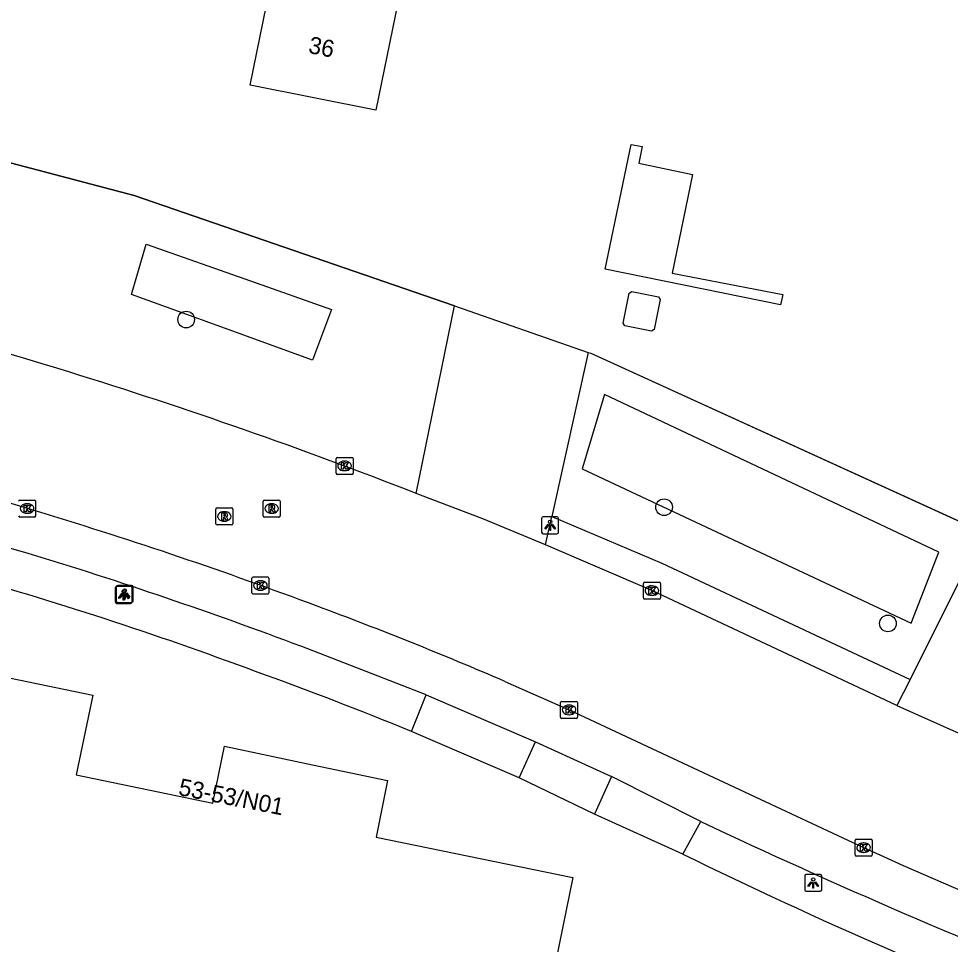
# Model space of a CAD drawing. Extents: x 157692 to 159670, y 381454 to 383289.
# Drawn here: x 158119.2 to 158173.9, y 381831.4 to 381885.7 of the extents above; entities that cross this region are included whole.
import ezdxf

# ---------------------------------------------------------------- set-up
doc = ezdxf.new("R2010")
doc.units = 0
for name, color, linetype in [('IMGEO_Berm_groen', 7, 'Continuous'), ('IMGEO_Boom', 7, 'Continuous'), ('IMGEO_Groenvoorziening', 7, 'Continuous'), ('IMGEO_Hek', 7, 'Continuous'), ('IMGEO_Kolk', 7, 'Continuous'), ('IMGEO_Lichtpunt', 7, 'Continuous'), ('IMGEO_Pand', 7, 'Continuous'), ('IMGEO_Pand_nummerreeks', 7, 'Continuous'), ('IMGEO_Rijbaan_lokaal_gesloten', 7, 'Continuous'), ('IMGEO_Rijbaan_lokaal_open', 7, 'Continuous'), ('IMGEO_Rioolput', 7, 'Continuous'), ('IMGEO_Voetpad_open', 7, 'Continuous'), ('IMGEO_Waterloop', 7, 'Continuous')]:
    doc.layers.add(name, color=color, linetype=linetype)

msp = doc.modelspace()

# ---------------------------------------------------------------- linework, layer by layer
at = {"layer": 'IMGEO_Berm_groen'}
msp.add_lwpolyline([(158144.779, 381868.849), (158125.96, 381875.333), (158105.527, 381880.719), (158105.432, 381880.499)], dxfattribs=at)
at = {"layer": 'IMGEO_Boom'}
for centre in [(158129.018, 381868.054), (158157.094, 381857.037), (158170.245, 381850.21)]:
    msp.add_circle(centre, 0.489, dxfattribs=at)
at = {"layer": 'IMGEO_Groenvoorziening'}
msp.add_lwpolyline([(158152.635, 381866.121), (158152.79, 381866.076), (158175.894, 381855.545)], dxfattribs=at)
at = {"layer": 'IMGEO_Hek'}
for points in [[(158105.432, 381880.499), (158105.527, 381880.719), (158125.96, 381875.333), (158144.779, 381868.849)], [(158144.779, 381868.849), (158152.635, 381866.121)], [(158152.635, 381866.121), (158152.79, 381866.076), (158181.715, 381852.892), (158201.637, 381844.863)]]:
    msp.add_lwpolyline(points, dxfattribs=at)
at = {"layer": 'IMGEO_Kolk'}
for p, q in [((158137.896, 381859.961), (158138.748, 381859.961)), ((158137.821, 381859.035), (158137.821, 381859.887)), ((158138.309, 381859.741), (158138.334, 381859.741)), ((158138.822, 381859.887), (158138.822, 381859.035)), ((158138.748, 381858.961), (158137.896, 381858.961)), ((158138.332, 381859.181), (158138.307, 381859.181)), ((158119.251, 381857.458), (158120.103, 381857.458)), ((158119.664, 381857.238), (158119.689, 381857.238)), ((158120.177, 381857.384), (158120.177, 381856.532)), ((158119.687, 381856.678), (158119.662, 381856.678)), ((158120.103, 381856.458), (158119.251, 381856.458)), ((158132.883, 381852.014), (158132.883, 381852.866)), ((158132.958, 381852.94), (158133.81, 381852.94)), ((158133.884, 381852.866), (158133.884, 381852.014)), ((158133.371, 381852.72), (158133.396, 381852.72)), ((158155.877, 381851.714), (158155.877, 381852.566)), ((158155.952, 381852.64), (158156.804, 381852.64)), ((158156.365, 381852.42), (158156.39, 381852.42)), ((158156.878, 381852.566), (158156.878, 381851.714)), ((158133.81, 381851.94), (158132.958, 381851.94)), ((158133.394, 381852.16), (158133.369, 381852.16)), ((158156.388, 381851.86), (158156.363, 381851.86)), ((158156.804, 381851.64), (158155.952, 381851.64)), ((158151.012, 381844.709), (158151.012, 381845.561)), ((158151.087, 381845.635), (158151.939, 381845.635)), ((158151.5, 381845.415), (158151.525, 381845.415)), ((158152.013, 381845.561), (158152.013, 381844.709)), ((158151.939, 381844.635), (158151.087, 381844.635)), ((158151.523, 381844.855), (158151.498, 381844.855)), ((158168.39, 381837.55), (158169.242, 381837.55)), ((158168.315, 381836.624), (158168.315, 381837.476)), ((158168.803, 381837.33), (158168.828, 381837.33)), ((158169.316, 381837.476), (158169.316, 381836.624)), ((158169.242, 381836.55), (158168.39, 381836.55)), ((158168.826, 381836.77), (158168.801, 381836.77))]:
    msp.add_line(p, q, dxfattribs=at)
for points in [[(158137.896, 381859.961), (158138.748, 381859.961)], [(158137.821, 381859.035), (158137.821, 381859.887)], [(158138.142, 381859.661), (158138.265, 381859.661), (158138.265, 381859.51), (158138.395, 381859.661), (158138.559, 381859.661), (158138.413, 381859.51), (158138.566, 381859.261), (158138.414, 381859.261), (158138.329, 381859.425), (158138.265, 381859.358), (158138.265, 381859.261), (158138.142, 381859.261), (158138.142, 381859.661)], [(158138.822, 381859.887), (158138.822, 381859.035)], [(158138.748, 381858.961), (158137.896, 381858.961)], [(158119.251, 381857.458), (158120.103, 381857.458)], [(158120.177, 381857.384), (158120.177, 381856.532)], [(158119.497, 381857.158), (158119.62, 381857.158), (158119.62, 381857.007), (158119.75, 381857.158), (158119.914, 381857.158), (158119.768, 381857.007), (158119.921, 381856.758), (158119.769, 381856.758), (158119.684, 381856.922), (158119.62, 381856.855), (158119.62, 381856.758), (158119.497, 381856.758), (158119.497, 381857.158)], [(158120.103, 381856.458), (158119.251, 381856.458)], [(158132.883, 381852.014), (158132.883, 381852.866)], [(158132.958, 381852.94), (158133.81, 381852.94)], [(158133.884, 381852.866), (158133.884, 381852.014)], [(158133.204, 381852.64), (158133.327, 381852.64), (158133.327, 381852.489), (158133.457, 381852.64), (158133.621, 381852.64), (158133.475, 381852.489), (158133.628, 381852.24), (158133.476, 381852.24), (158133.391, 381852.404), (158133.327, 381852.337), (158133.327, 381852.24), (158133.204, 381852.24), (158133.204, 381852.64)], [(158155.877, 381851.714), (158155.877, 381852.566)], [(158155.952, 381852.64), (158156.804, 381852.64)], [(158156.198, 381852.34), (158156.321, 381852.34), (158156.321, 381852.189), (158156.451, 381852.34), (158156.615, 381852.34), (158156.469, 381852.189), (158156.622, 381851.94), (158156.47, 381851.94), (158156.385, 381852.104), (158156.321, 381852.037), (158156.321, 381851.94), (158156.198, 381851.94), (158156.198, 381852.34)], [(158156.878, 381852.566), (158156.878, 381851.714)], [(158133.81, 381851.94), (158132.958, 381851.94)], [(158156.804, 381851.64), (158155.952, 381851.64)], [(158151.012, 381844.709), (158151.012, 381845.561)], [(158151.087, 381845.635), (158151.939, 381845.635)], [(158151.333, 381845.335), (158151.456, 381845.335), (158151.456, 381845.184), (158151.586, 381845.335), (158151.75, 381845.335), (158151.604, 381845.184), (158151.757, 381844.935), (158151.605, 381844.935), (158151.52, 381845.099), (158151.456, 381845.032), (158151.456, 381844.935), (158151.333, 381844.935), (158151.333, 381845.335)], [(158152.013, 381845.561), (158152.013, 381844.709)], [(158151.939, 381844.635), (158151.087, 381844.635)], [(158168.39, 381837.55), (158169.242, 381837.55)], [(158168.315, 381836.624), (158168.315, 381837.476)], [(158168.636, 381837.25), (158168.759, 381837.25), (158168.759, 381837.099), (158168.889, 381837.25), (158169.053, 381837.25), (158168.907, 381837.099), (158169.06, 381836.85), (158168.908, 381836.85), (158168.823, 381837.014), (158168.759, 381836.947), (158168.759, 381836.85), (158168.636, 381836.85), (158168.636, 381837.25)], [(158169.316, 381837.476), (158169.316, 381836.624)], [(158169.242, 381836.55), (158168.39, 381836.55)]]:
    msp.add_lwpolyline(points, dxfattribs=at)
for centre, start, end in [((158137.898, 381859.885), 91.552, 178.448), ((158137.898, 381859.885), 91.552, 178.448), ((158138.746, 381859.885), 1.552, 88.448), ((158138.746, 381859.885), 1.552, 88.448), ((158137.898, 381859.037), 181.552, 268.448), ((158137.898, 381859.037), 181.552, 268.448), ((158138.746, 381859.037), 271.552, 358.448), ((158138.746, 381859.037), 271.552, 358.448), ((158119.253, 381857.382), 91.552, 178.448), ((158119.253, 381857.382), 91.552, 178.448), ((158120.101, 381857.382), 1.552, 88.448), ((158120.101, 381857.382), 1.552, 88.448), ((158119.253, 381856.534), 181.552, 268.448), ((158119.253, 381856.534), 181.552, 268.448), ((158120.101, 381856.534), 271.552, 358.448), ((158120.101, 381856.534), 271.552, 358.448), ((158132.96, 381852.864), 91.552, 178.448), ((158132.96, 381852.864), 91.552, 178.448), ((158133.808, 381852.864), 1.552, 88.448), ((158133.808, 381852.864), 1.552, 88.448), ((158155.954, 381852.564), 91.552, 178.448), ((158155.954, 381852.564), 91.552, 178.448), ((158156.802, 381852.564), 1.552, 88.448), ((158156.802, 381852.564), 1.552, 88.448), ((158132.96, 381852.016), 181.552, 268.448), ((158132.96, 381852.016), 181.552, 268.448), ((158133.808, 381852.016), 271.552, 358.448), ((158133.808, 381852.016), 271.552, 358.448), ((158155.954, 381851.716), 181.552, 268.448), ((158155.954, 381851.716), 181.552, 268.448), ((158156.802, 381851.716), 271.552, 358.448), ((158156.802, 381851.716), 271.552, 358.448), ((158151.089, 381845.559), 91.552, 178.448), ((158151.089, 381845.559), 91.552, 178.448), ((158151.937, 381845.559), 1.552, 88.448), ((158151.937, 381845.559), 1.552, 88.448), ((158151.089, 381844.711), 181.552, 268.448), ((158151.089, 381844.711), 181.552, 268.448), ((158151.937, 381844.711), 271.552, 358.448), ((158151.937, 381844.711), 271.552, 358.448), ((158168.392, 381837.474), 91.552, 178.448), ((158168.392, 381837.474), 91.552, 178.448), ((158169.24, 381837.474), 1.552, 88.448), ((158169.24, 381837.474), 1.552, 88.448), ((158168.392, 381836.626), 181.552, 268.448), ((158168.392, 381836.626), 181.552, 268.448), ((158169.24, 381836.626), 271.552, 358.448), ((158169.24, 381836.626), 271.552, 358.448)]:
    msp.add_arc(centre, 0.0765, start, end, dxfattribs=at)
for centre, major_axis, ratio, start_param, end_param in [((158138.308, 381859.461), (-0.387, 0.002), 0.722429, 4.712389, 7.853982), ((158138.333, 381859.461), (-0.39, 0.002), 0.717154, 1.570796, 4.712389), ((158119.663, 381856.958), (-0.387, 0.002), 0.722429, 4.712389, 7.853982), ((158119.688, 381856.958), (-0.39, 0.002), 0.717154, 1.570796, 4.712389), ((158133.37, 381852.44), (-0.387, 0.002), 0.722429, 4.712389, 7.853982), ((158133.395, 381852.44), (-0.39, 0.002), 0.717154, 1.570796, 4.712389), ((158156.364, 381852.14), (-0.387, 0.002), 0.722429, 4.712389, 7.853982), ((158156.389, 381852.14), (-0.39, 0.002), 0.717154, 1.570796, 4.712389), ((158151.499, 381845.135), (-0.387, 0.002), 0.722429, 4.712389, 7.853982), ((158151.524, 381845.135), (-0.39, 0.002), 0.717154, 1.570796, 4.712389), ((158168.802, 381837.05), (-0.387, 0.002), 0.722429, 4.712389, 7.853982), ((158168.827, 381837.05), (-0.39, 0.002), 0.717154, 1.570796, 4.712389)]:
    msp.add_ellipse(centre, major_axis=major_axis, ratio=ratio, start_param=start_param, end_param=end_param, dxfattribs=at)
at = {"layer": 'IMGEO_Lichtpunt'}
for p, q in [((158149.902, 381856.378), (158149.902, 381855.571)), ((158149.902, 381856.378), (158149.902, 381855.571)), ((158150.804, 381856.473), (158149.996, 381856.473)), ((158150.804, 381856.473), (158149.996, 381856.473)), ((158150.898, 381855.571), (158150.898, 381856.378)), ((158150.898, 381855.571), (158150.898, 381856.378)), ((158149.996, 381855.477), (158150.804, 381855.477)), ((158149.996, 381855.477), (158150.804, 381855.477)), ((158124.851, 381852.293), (158124.851, 381851.486)), ((158124.851, 381852.293), (158124.851, 381851.486)), ((158124.907, 381852.349), (158124.907, 381851.542)), ((158124.907, 381852.349), (158124.907, 381851.542)), ((158125.753, 381852.388), (158124.945, 381852.388)), ((158125.753, 381852.388), (158124.945, 381852.388)), ((158125.809, 381852.444), (158125.001, 381852.444)), ((158125.809, 381852.444), (158125.001, 381852.444)), ((158125.847, 381851.486), (158125.847, 381852.293)), ((158125.847, 381851.486), (158125.847, 381852.293)), ((158125.903, 381851.542), (158125.903, 381852.349)), ((158125.903, 381851.542), (158125.903, 381852.349)), ((158124.945, 381851.392), (158125.753, 381851.392)), ((158124.945, 381851.392), (158125.753, 381851.392)), ((158125.001, 381851.448), (158125.809, 381851.448)), ((158125.001, 381851.448), (158125.809, 381851.448)), ((158165.357, 381835.385), (158165.357, 381834.578)), ((158165.357, 381835.385), (158165.357, 381834.578)), ((158166.259, 381835.48), (158165.451, 381835.48)), ((158166.259, 381835.48), (158165.451, 381835.48)), ((158166.353, 381834.578), (158166.353, 381835.385)), ((158166.353, 381834.578), (158166.353, 381835.385)), ((158165.451, 381834.484), (158166.259, 381834.484)), ((158165.451, 381834.484), (158166.259, 381834.484))]:
    msp.add_line(p, q, dxfattribs=at)
for points in [[(158150.276, 381856.042), (158150.315, 381856.014), (158150.127, 381855.752), (158150.089, 381855.779), (158150.276, 381856.042)], [(158150.378, 381855.994), (158150.425, 381855.994), (158150.425, 381855.672), (158150.378, 381855.672), (158150.378, 381855.994)], [(158150.488, 381856.014), (158150.526, 381856.041), (158150.713, 381855.779), (158150.674, 381855.751), (158150.488, 381856.014)], [(158125.225, 381851.957), (158125.264, 381851.929), (158125.076, 381851.667), (158125.038, 381851.694), (158125.225, 381851.957)], [(158125.281, 381852.013), (158125.32, 381851.985), (158125.132, 381851.723), (158125.094, 381851.75), (158125.281, 381852.013)], [(158125.327, 381851.909), (158125.374, 381851.909), (158125.374, 381851.587), (158125.327, 381851.587), (158125.327, 381851.909)], [(158125.383, 381851.965), (158125.43, 381851.965), (158125.43, 381851.643), (158125.383, 381851.643), (158125.383, 381851.965)], [(158125.437, 381851.929), (158125.475, 381851.956), (158125.662, 381851.694), (158125.623, 381851.666), (158125.437, 381851.929)], [(158125.493, 381851.985), (158125.531, 381852.012), (158125.718, 381851.75), (158125.679, 381851.722), (158125.493, 381851.985)], [(158165.731, 381835.049), (158165.77, 381835.021), (158165.582, 381834.759), (158165.544, 381834.786), (158165.731, 381835.049)], [(158165.833, 381835.001), (158165.88, 381835.001), (158165.88, 381834.679), (158165.833, 381834.679), (158165.833, 381835.001)], [(158165.943, 381835.021), (158165.981, 381835.048), (158166.168, 381834.786), (158166.129, 381834.758), (158165.943, 381835.021)]]:
    msp.add_lwpolyline(points, dxfattribs=at)
for centre in [(158150.401, 381856.176), (158125.35, 381852.091), (158125.406, 381852.147), (158165.856, 381835.183)]:
    msp.add_circle(centre, 0.0994, dxfattribs=at)
for centre, start, end in [((158149.996, 381856.378), 90, 180), ((158149.996, 381856.378), 90, 180), ((158150.804, 381856.378), 0, 90), ((158150.804, 381856.378), 0, 90), ((158149.996, 381855.571), 180, 270), ((158149.996, 381855.571), 180, 270), ((158150.804, 381855.571), 270, 0), ((158150.804, 381855.571), 270, 360), ((158124.945, 381852.293), 90, 180), ((158124.945, 381852.293), 90, 180), ((158125.001, 381852.349), 90, 180), ((158125.001, 381852.349), 90, 180), ((158125.753, 381852.293), 0, 90), ((158125.753, 381852.293), 0, 90), ((158125.809, 381852.349), 0, 90), ((158125.809, 381852.349), 0, 90), ((158124.945, 381851.486), 180, 270), ((158124.945, 381851.486), 180, 270), ((158125.001, 381851.542), 180, 270), ((158125.001, 381851.542), 180, 270), ((158125.753, 381851.486), 270, 0), ((158125.753, 381851.486), 270, 360), ((158125.809, 381851.542), 270, 0), ((158125.809, 381851.542), 270, 360), ((158165.451, 381835.385), 90, 180), ((158165.451, 381835.385), 90, 180), ((158166.259, 381835.385), 0, 90), ((158166.259, 381835.385), 0, 90), ((158165.451, 381834.578), 180, 270), ((158165.451, 381834.578), 180, 270), ((158166.259, 381834.578), 270, 0), ((158166.259, 381834.578), 270, 360)]:
    msp.add_arc(centre, 0.0946, start, end, dxfattribs=at)
at = {"layer": 'IMGEO_Pand'}
for points in [[(158150.089, 381901.741), (158149.404, 381898.409), (158148.396, 381893.511), (158143.672, 381890.398), (158142.279, 381890.684), (158140.153, 381880.347), (158132.778, 381881.818), (158134.901, 381892.186), (158133.538, 381892.467), (158130.421, 381897.187), (158131.806, 381903.957)], [(158164.062, 381869.533), (158163.943, 381868.909), (158153.641, 381871.004), (158155.165, 381878.336), (158155.808, 381878.218), (158155.605, 381877.228), (158158.771, 381876.571), (158157.567, 381870.772), (158164.062, 381869.533)], [(158156.503, 381867.463), (158156.361, 381867.369), (158154.784, 381867.69), (158154.69, 381867.832), (158155.051, 381869.606), (158155.193, 381869.7), (158156.77, 381869.379), (158156.864, 381869.237), (158156.503, 381867.463)], [(158102.734, 381825.813), (158104.044, 381832.191), (158104.164, 381832.773), (158101.359, 381833.35), (158101.783, 381835.271), (158097.517, 381836.193), (158098.197, 381839.516), (158100.733, 381851.905), (158112.978, 381849.405), (158112.74, 381848.239), (158123.532, 381845.992), (158122.559, 381841.327), (158130.579, 381839.658), (158131.276, 381843.007), (158136.07, 381841.995), (158140.855, 381840.985), (158140.175, 381837.654), (158151.738, 381835.295), (158150.734, 381830.397)]]:
    msp.add_lwpolyline(points, dxfattribs=at)
at = {"layer": 'IMGEO_Rijbaan_lokaal_gesloten'}
for points in [[(158150.122, 381854.82), (158146.45, 381856.345), (158142.538, 381857.841)], [(158170.769, 381845.392), (158156.373, 381852.139), (158150.122, 381854.82)], [(158147.745, 381846.806), (158151.513, 381845.136), (158168.817, 381837.051)], [(158170.769, 381845.392), (158176.956, 381842.64)]]:
    msp.add_lwpolyline(points, dxfattribs=at)
for centre, radius, start, end in [((158031.345, 381570.921), 307.747, 72.84363, 75.67633), ((158034.958, 381582.775), 295.355, 68.63927, 72.83516), ((157995.02, 381438.686), 436.461, 73.29584, 75.53852), ((158042.286, 381599.33), 269.011, 69.45154, 73.10364), ((158056.18, 381634.171), 231.512, 66.70229, 69.64477), ((158293.532, 382111.805), 301.735, 245.58593, 253.34762)]:
    msp.add_arc(centre, radius, start, end, dxfattribs=at)
at = {"layer": 'IMGEO_Rijbaan_lokaal_open'}
for points in [[(158142.538, 381857.841), (158144.779, 381868.849)], [(158144.779, 381868.849), (158152.635, 381866.121)], [(158152.635, 381866.121), (158150.495, 381856.499)], [(158150.122, 381854.82), (158150.495, 381856.499)], [(158171.542, 381846.928), (158175.726, 381855.243), (158175.894, 381855.545)], [(158171.542, 381846.928), (158170.769, 381845.392)]]:
    msp.add_lwpolyline(points, dxfattribs=at)
at = {"layer": 'IMGEO_Rioolput'}
for p, q in [((158133.538, 381856.531), (158133.538, 381857.383)), ((158133.613, 381857.457), (158134.465, 381857.457)), ((158134.026, 381857.237), (158134.051, 381857.237)), ((158134.539, 381857.383), (158134.539, 381856.531)), ((158130.761, 381856.068), (158130.761, 381856.92)), ((158130.836, 381856.994), (158131.688, 381856.994)), ((158131.249, 381856.774), (158131.274, 381856.774)), ((158131.762, 381856.92), (158131.762, 381856.068)), ((158134.049, 381856.677), (158134.024, 381856.677)), ((158131.272, 381856.214), (158131.247, 381856.214)), ((158134.465, 381856.457), (158133.613, 381856.457)), ((158131.688, 381855.994), (158130.836, 381855.994))]:
    msp.add_line(p, q, dxfattribs=at)
for points in [[(158133.538, 381856.531), (158133.538, 381857.383)], [(158133.613, 381857.457), (158134.465, 381857.457)], [(158134.539, 381857.383), (158134.539, 381856.531)], [(158130.761, 381856.068), (158130.761, 381856.92)], [(158130.836, 381856.994), (158131.688, 381856.994)], [(158131.35, 381856.692), (158131.098, 381856.694), (158131.098, 381856.294)], [(158131.762, 381856.92), (158131.762, 381856.068)], [(158134.127, 381857.155), (158133.875, 381857.157), (158133.875, 381856.757)], [(158133.875, 381856.757), (158133.999, 381856.757), (158133.999, 381856.919), (158134.01, 381856.919)], [(158134.053, 381857.076), (158133.999, 381857.076), (158133.999, 381856.995)], [(158133.999, 381856.995), (158134.051, 381856.995)], [(158134.057, 381856.89), (158134.128, 381856.757), (158134.268, 381856.757), (158134.203, 381856.883)], [(158131.098, 381856.294), (158131.222, 381856.294), (158131.222, 381856.456), (158131.233, 381856.456)], [(158131.276, 381856.613), (158131.222, 381856.613), (158131.222, 381856.532)], [(158131.222, 381856.532), (158131.274, 381856.532)], [(158131.28, 381856.427), (158131.351, 381856.294), (158131.491, 381856.294), (158131.426, 381856.42)], [(158134.465, 381856.457), (158133.613, 381856.457)], [(158131.688, 381855.994), (158130.836, 381855.994)]]:
    msp.add_lwpolyline(points, dxfattribs=at)
for centre, radius, start, end in [((158133.615, 381857.381), 0.0765, 91.552, 178.448), ((158133.615, 381857.381), 0.0765, 91.552, 178.448), ((158134.463, 381857.381), 0.0765, 1.552, 88.448), ((158134.463, 381857.381), 0.0765, 1.552, 88.448), ((158130.838, 381856.918), 0.0765, 91.552, 178.448), ((158130.838, 381856.918), 0.0765, 91.552, 178.448), ((158131.349, 381856.582), 0.109, 350.3612, 89.416), ((158131.686, 381856.918), 0.0765, 1.552, 88.448), ((158131.686, 381856.918), 0.0765, 1.552, 88.448), ((158134.009, 381856.866), 0.0533, 26.0293, 88.6989), ((158134.035, 381857.184), 0.19, 274.7715, 282.9687), ((158134.059, 381856.98), 0.0964, 77.0061, 93.1865), ((158134.073, 381857.037), 0.0378, 276.6634, 79.6772), ((158134.126, 381857.045), 0.109, 350.3612, 89.416), ((158134.124, 381857.045), 0.112, 277.5842, 350.9817), ((158134.108, 381856.83), 0.108, 29.5134, 73.7905), ((158131.232, 381856.403), 0.0533, 26.0293, 88.6989), ((158131.258, 381856.721), 0.19, 274.7715, 282.9687), ((158131.282, 381856.517), 0.0964, 77.0061, 93.1865), ((158131.296, 381856.574), 0.0378, 276.6634, 79.6772), ((158131.347, 381856.582), 0.112, 277.5842, 350.9817), ((158131.331, 381856.367), 0.108, 29.5134, 73.7905), ((158133.615, 381856.533), 0.0765, 181.552, 268.448), ((158133.615, 381856.533), 0.0765, 181.552, 268.448), ((158134.463, 381856.533), 0.0765, 271.552, 358.448), ((158134.463, 381856.533), 0.0765, 271.552, 358.448), ((158130.838, 381856.07), 0.0765, 181.552, 268.448), ((158130.838, 381856.07), 0.0765, 181.552, 268.448), ((158131.686, 381856.07), 0.0765, 271.552, 358.448), ((158131.686, 381856.07), 0.0765, 271.552, 358.448)]:
    msp.add_arc(centre, radius, start, end, dxfattribs=at)
for centre, major_axis, ratio, start_param, end_param in [((158134.025, 381856.957), (-0.387, 0.002), 0.722429, 4.712389, 7.853982), ((158134.05, 381856.957), (-0.39, 0.002), 0.717154, 1.570796, 4.712389), ((158131.248, 381856.494), (-0.387, 0.002), 0.722429, 4.712389, 7.853982), ((158131.273, 381856.494), (-0.39, 0.002), 0.717154, 1.570796, 4.712389)]:
    msp.add_ellipse(centre, major_axis=major_axis, ratio=ratio, start_param=start_param, end_param=end_param, dxfattribs=at)
at = {"layer": 'IMGEO_Voetpad_open'}
for points in [[(158119.745, 381854.323), (158107.306, 381857.884)], [(158150.495, 381856.499), (158156.953, 381853.746), (158171.542, 381846.928)], [(158143.124, 381846.013), (158135.804, 381848.857)], [(158142.249, 381843.867), (158143.124, 381846.013)], [(158143.124, 381846.013), (158149.548, 381843.263)], [(158148.581, 381841.149), (158142.249, 381843.867)], [(158148.581, 381841.149), (158149.548, 381843.263)], [(158149.548, 381843.263), (158154.003, 381841.223)], [(158153.013, 381839.008), (158148.581, 381841.149)], [(158154.003, 381841.223), (158153.013, 381839.008)], [(158159.249, 381838.585), (158154.003, 381841.223)], [(158158.188, 381836.67), (158153.013, 381839.008)], [(158158.188, 381836.67), (158159.249, 381838.585)]]:
    msp.add_lwpolyline(points, dxfattribs=at)
for centre, radius, start, end in [((158040.633, 381595.569), 270.578, 69.40662, 72.99933), ((158054.025, 381634.974), 226.658, 69.58203, 74.34294), ((158058.571, 381640.219), 220.17, 67.66253, 70.21463), ((158324.825, 382189.32), 387.854, 244.72884, 248.6019), ((158299.7, 382126.88), 322.874, 244.00529, 248.69973)]:
    msp.add_arc(centre, radius, start, end, dxfattribs=at)
at = {"layer": 'IMGEO_Waterloop'}
for points in [[(158126.665, 381872.472), (158132.789, 381870.317), (158137.55, 381868.642), (158136.449, 381865.673), (158131.754, 381867.372), (158125.803, 381869.525), (158126.665, 381872.472)], [(158171.62, 381850.221), (158173.23, 381854.387), (158153.602, 381863.648), (158152.275, 381859.287), (158171.62, 381850.221)]]:
    msp.add_lwpolyline(points, dxfattribs=at)

# ---------------------------------------------------------------- texts
at = {"layer": 'IMGEO_Pand_nummerreeks'}
for s, rotation, p in [('36', 348.7185, (158136.149, 381883.715)), ('53-53/N01', 348.8785, (158128.518, 381840.145))]:
    msp.add_text(s, height=1, rotation=rotation, dxfattribs=at).set_placement(p)

doc.saveas('drawing.dxf')
